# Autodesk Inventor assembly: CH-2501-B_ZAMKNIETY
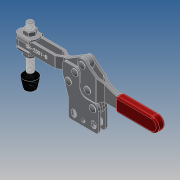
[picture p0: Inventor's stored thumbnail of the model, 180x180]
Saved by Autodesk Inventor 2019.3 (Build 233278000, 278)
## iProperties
Company: Î¢ÈíÖÐ¹ú
Created: 2012-09
Part Number: CH-2501-B_ZAMKNIETY
Material: Ogólny
Description: STEP AP203
Document SubType Name: Assembly
Designer: CADENGINEERING4
Sending System: SolidWorks 2010
Preprocessor: SwSTEP 2.0
Title: CH-2501-B.STEP
Author: Î¢ÈíÓÃ»§
Revision Number: ÈÎºÎ
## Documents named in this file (12)
- E:\STRONA\Horizontal toggle clamp\CH-2501-B\CH-2501-B_ZAMKNIETY.iam
- E:\STRONA\Horizontal toggle clamp\CH-2501-B\CH-FC-56300-02____1.ipt
- E:\STRONA\Horizontal toggle clamp\CH-2501-B\CH-FC-56300____1.ipt
- E:\STRONA\Horizontal toggle clamp\CH-2501-B\CH-2500-04____1.ipt
- E:\STRONA\Horizontal toggle clamp\CH-2501-B\CH-36092M-06____1.ipt
- E:\STRONA\Horizontal toggle clamp\CH-2501-B\CH-2501-B-02___.ipt
- E:\STRONA\Horizontal toggle clamp\CH-2501-B\CH-2500-05____1.ipt
- E:\STRONA\Horizontal toggle clamp\CH-2501-B\CH-2500-06____1.ipt
- E:\STRONA\Horizontal toggle clamp\CH-2501-B\FW516____1.ipt
- E:\STRONA\Horizontal toggle clamp\CH-2501-B\CH-2500-03____1.ipt
- E:\STRONA\Horizontal toggle clamp\CH-2501-B\CH-11401-05____1.ipt
- E:\STRONA\Horizontal toggle clamp\CH-2501-B\CH-2501-B-01___.ipt
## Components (20 placed, 20 different names)
1. CH-FC-56300-02____1_1 — Zestawiające:7, Zestawiające:8, Równoległe:2
2. CH-FC-56300____1_2 — Zestawiające:3, Zestawiające:4, Zestawiające:6, Zestawiające:7, Równoległe:2, Zestawiające:11
3. CH-2500-04____1_3 — Zestawiające:22, Zestawiające:23, Zestawiające:24, Równoległe:3, Zestawiające:25
4. CH-36092M-06____1_4 — Zestawiające:18, Zestawiające:19
5. CH-2501-B-02____5 — Zestawiające:2, Zestawiające:9, Zestawiające:10, Zestawiające:11, Zestawiające:37, Zestawiające:38, Zestawiające:39
6. CH-2500-05____1_6 — Zestawiające:1, Zestawiające:12, Zestawiające:13
7. CH-2500-06____1_7 — Zestawiające:35, Zestawiające:36, Zestawiające:38
8. FW516____1_8 — Zestawiające:2, Równoległe:1, Zestawiające:6, Zestawiające:8, Zestawiające:10
9. CH-FC-56300-02____1_9 — Zestawiające:3, Zestawiające:5
10. CH-2500-03____1_10 — Zestawiające:1, Zestawiające:12, Zestawiające:13, Zestawiające:14, Zestawiające:15, Zestawiające:16, Zestawiające:17, Zestawiające:25, Zestawiające:26, Zestawiające:27, Zestawiające:28, Przejściowe:1
11. CH-11401-05____1_11 — Zestawiające:29, Zestawiające:30
12. CH-2500-06____1_12 — Zestawiające:20, Zestawiające:21, Zestawiające:23
13. FW516____1_13 — Równoległe:1, Zestawiające:4, Zestawiające:5, Zestawiające:9
14. CH-2500-06____1_14 — Zestawiające:16, Zestawiające:17, Zestawiające:39
15. CH-36092M-06____1_15 — Zestawiające:14, Zestawiające:15
16. CH-2501-B-01____16 — Zestawiające:18, Zestawiające:19, Zestawiające:20, Zestawiające:21, Zestawiające:22, Zestawiające:29, Zestawiające:30, Zestawiające:31, Zestawiające:32, Zestawiające:33, Zestawiające:34, Zestawiające:35, Zestawiające:36, Zestawiające:37, Przejściowe:1
17. CH-2500-06____1_17 — Zestawiające:31, Zestawiające:32
18. CH-2500-06____1_18 — Zestawiające:27, Zestawiające:28
19. CH-36092M-06____1_19 — Zestawiające:24, Równoległe:3, Zestawiające:26
20. CH-36092M-06____1_20 — Zestawiające:33, Zestawiające:34
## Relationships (43: Mate 39, Flush 3, Transitional 1)
- Zestawiające:1 [Mate]: CH-2500-05____1_6 ↔ CH-2500-03____1_10
- Zestawiające:2 [Mate]: CH-2501-B-02____5 ↔ FW516____1_8
- Równoległe:1 [Flush]: FW516____1_8 ↔ FW516____1_13
- Zestawiające:3 [Mate]: CH-FC-56300____1_2 ↔ CH-FC-56300-02____1_9
- Zestawiające:4 [Mate]: CH-FC-56300____1_2 ↔ FW516____1_13
- Zestawiające:5 [Mate]: CH-FC-56300-02____1_9 ↔ FW516____1_13
- Zestawiające:6 [Mate]: CH-FC-56300____1_2 ↔ FW516____1_8
- Zestawiające:7 [Mate]: CH-FC-56300-02____1_1 ↔ CH-FC-56300____1_2
- Zestawiające:8 [Mate]: CH-FC-56300-02____1_1 ↔ FW516____1_8
- Zestawiające:9 [Mate]: CH-2501-B-02____5 ↔ FW516____1_13
- Zestawiające:10 [Mate]: CH-2501-B-02____5 ↔ FW516____1_8
- Równoległe:2 [Flush]: CH-FC-56300-02____1_1 ↔ CH-FC-56300____1_2
- Zestawiające:11 [Mate]: CH-FC-56300____1_2 ↔ CH-2501-B-02____5
- Zestawiające:12 [Mate]: CH-2500-05____1_6 ↔ CH-2500-03____1_10
- Zestawiające:13 [Mate]: CH-2500-05____1_6 ↔ CH-2500-03____1_10
- Zestawiające:14 [Mate]: CH-2500-03____1_10 ↔ CH-36092M-06____1_15
- Zestawiające:15 [Mate]: CH-2500-03____1_10 ↔ CH-36092M-06____1_15
- Zestawiające:16 [Mate]: CH-2500-03____1_10 ↔ CH-2500-06____1_14
- Zestawiające:17 [Mate]: CH-2500-03____1_10 ↔ CH-2500-06____1_14
- Zestawiające:18 [Mate]: CH-36092M-06____1_4 ↔ CH-2501-B-01____16
- Zestawiające:19 [Mate]: CH-36092M-06____1_4 ↔ CH-2501-B-01____16
- Zestawiające:20 [Mate]: CH-2500-06____1_12 ↔ CH-2501-B-01____16
- Zestawiające:21 [Mate]: CH-2500-06____1_12 ↔ CH-2501-B-01____16
- Zestawiające:22 [Mate]: CH-2500-04____1_3 ↔ CH-2501-B-01____16
- Zestawiające:23 [Mate]: CH-2500-04____1_3 ↔ CH-2500-06____1_12
- Zestawiające:24 [Mate]: CH-2500-04____1_3 ↔ CH-36092M-06____1_19
- Równoległe:3 [Flush]: CH-2500-04____1_3 ↔ CH-36092M-06____1_19
- Zestawiające:25 [Mate]: CH-2500-04____1_3 ↔ CH-2500-03____1_10
- Zestawiające:26 [Mate]: CH-2500-03____1_10 ↔ CH-36092M-06____1_19
- Zestawiające:27 [Mate]: CH-2500-03____1_10 ↔ CH-2500-06____1_18
- Zestawiające:28 [Mate]: CH-2500-03____1_10 ↔ CH-2500-06____1_18
- Zestawiające:29 [Mate]: CH-11401-05____1_11 ↔ CH-2501-B-01____16
- Zestawiające:30 [Mate]: CH-11401-05____1_11 ↔ CH-2501-B-01____16
- Zestawiające:31 [Mate]: CH-2501-B-01____16 ↔ CH-2500-06____1_17
- Zestawiające:32 [Mate]: CH-2501-B-01____16 ↔ CH-2500-06____1_17
- Zestawiające:33 [Mate]: CH-2501-B-01____16 ↔ CH-36092M-06____1_20
- Zestawiające:34 [Mate]: CH-2501-B-01____16 ↔ CH-36092M-06____1_20
- Zestawiające:35 [Mate]: CH-2500-06____1_7 ↔ CH-2501-B-01____16
- Zestawiające:36 [Mate]: CH-2500-06____1_7 ↔ CH-2501-B-01____16
- Zestawiające:37 [Mate]: CH-2501-B-02____5 ↔ CH-2501-B-01____16
- Zestawiające:38 [Mate]: CH-2501-B-02____5 ↔ CH-2500-06____1_7
- Zestawiające:39 [Mate]: CH-2501-B-02____5 ↔ CH-2500-06____1_14
- Przejściowe:1 [Transitional]: CH-2500-03____1_10 ↔ CH-2501-B-01____16
